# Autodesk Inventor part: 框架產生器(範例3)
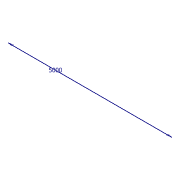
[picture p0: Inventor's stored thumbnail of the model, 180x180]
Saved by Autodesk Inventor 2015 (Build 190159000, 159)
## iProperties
Created: 2019-08
Part Number: 框架產生器(範例3)
Material: 一般
Document SubType Name: Modeling
Designer: Kuan_Lun Hsu
Density: 1 g/cm^3
Appearance: 預設
Author: Kuan_Lun Hsu
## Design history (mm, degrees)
sketch "草圖1"
  geometry: L1 (0, 0)-(5000, 0)
  constraints: 2 end point, 1 horizontal
  dimensions: "d0" = 5000 dimension on L1.start L1.end L1; "d0" = 5000 distance of L1.start L1.end
